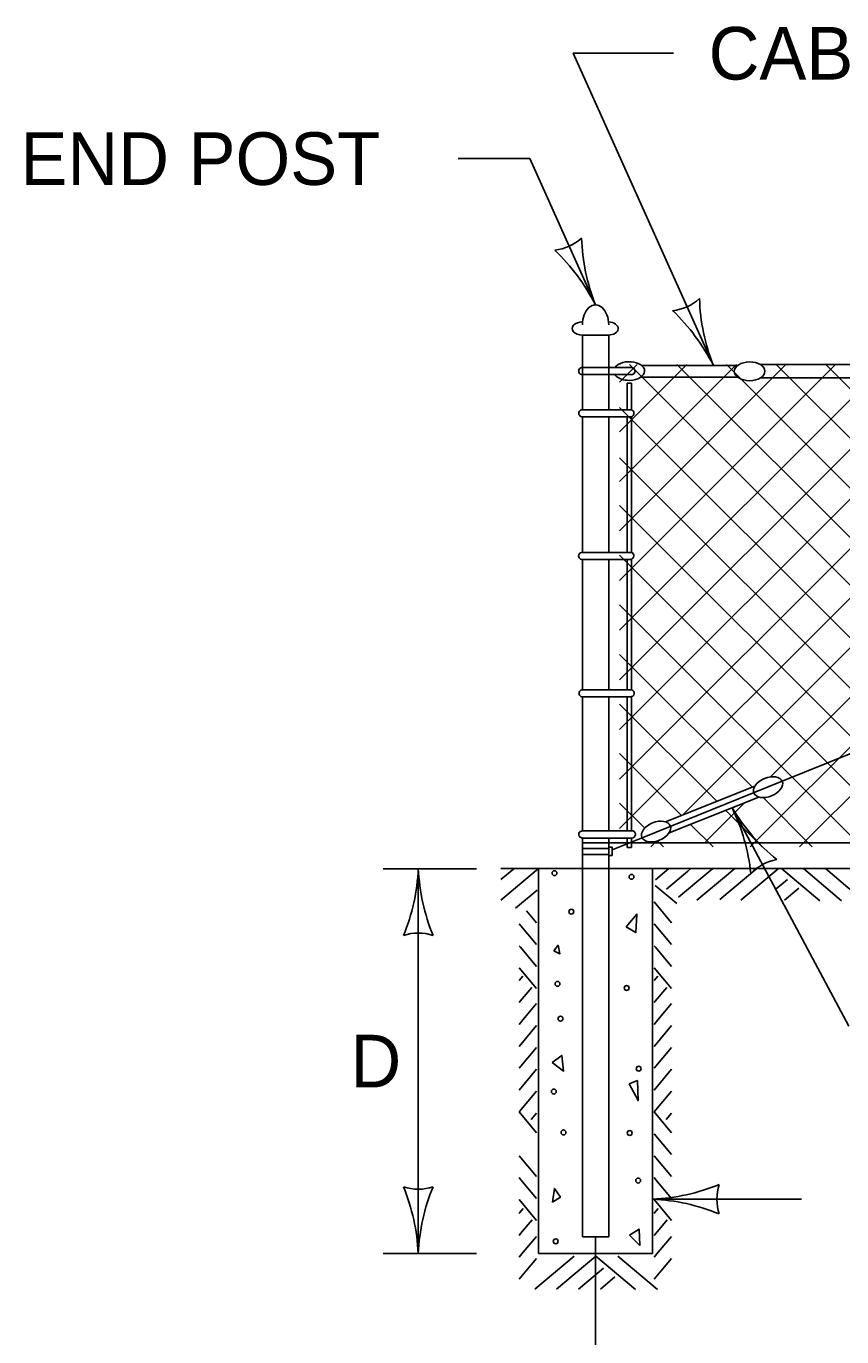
# Model space of a CAD drawing. Extents: x 49973.1 to 50021, y 49987.6 to 50015.4.
# Drawn here: x 49973.089 to 49974.019, y 50008.477 to 50009.972 of the extents above; entities that cross this region are included whole.
import ezdxf

# ---------------------------------------------------------------- set-up
doc = ezdxf.new("R2010")
doc.units = 0
for name, color, linetype in [('Level 1', 7, 'Continuous'), ('Level 2', 7, 'Continuous'), ('Level 3', 7, 'Continuous')]:
    doc.layers.add(name, color=color, linetype=linetype)

msp = doc.modelspace()

# ---------------------------------------------------------------- linework, layer by layer
at = {"layer": 'Level 1'}
for p, q in [((49973.7532, 50009.6195), (49973.7232, 50009.6195)), ((49973.7232, 50009.6195), (49973.7232, 50009.5341)), ((49973.7532, 50009.6195), (49973.7532, 50009.5341)), ((49973.7792, 50009.5824), (49973.7221, 50009.5824)), ((49973.7657, 50009.2828), (49974.0686, 50009.5857)), ((49973.7657, 50009.113), (49974.2384, 50009.5857)), ((49973.7657, 50009.2262), (49974.1252, 50009.5857)), ((49973.7657, 50009.1696), (49974.1818, 50009.5857)), ((49973.7657, 50009.0566), (49974.2948, 50009.5857)), ((49973.7657, 50009.509), (49973.8424, 50009.5857)), ((49973.7657, 50009.396), (49973.9554, 50009.5857)), ((49973.7657, 50009.4526), (49973.8988, 50009.5857)), ((49973.7657, 50009.5656), (49973.7858, 50009.5857)), ((49973.7657, 50009.3394), (49974.012, 50009.5857)), ((49973.7769, 50009.5857), (49974.3269, 50009.0357)), ((49973.9004, 50009.5848), (49973.7908, 50009.5847)), ((49973.8311, 50009.5857), (49974.3811, 50009.0357)), ((49973.8378, 50009.0721), (49974.3514, 50009.5857)), ((49973.8876, 50009.5857), (49974.0138, 50009.4595)), ((49973.9146, 50009.0357), (49974.4646, 50009.5857)), ((49973.9263, 50009.5857), (49975.6696, 50009.5857)), ((49973.9377, 50009.1154), (49974.408, 50009.5857)), ((49973.9443, 50009.5857), (49974.0683, 50009.4618)), ((49973.971, 50009.0357), (49974.521, 50009.5857)), ((49974.0009, 50009.5857), (49974.5509, 50009.0357)), ((49973.7792, 50009.5743), (49973.7223, 50009.5743)), ((49973.7742, 50009.5647), (49973.7742, 50009.5341)), ((49973.7792, 50009.5647), (49973.7742, 50009.5647)), ((49973.7792, 50009.5647), (49973.7792, 50009.5341)), ((49973.9002, 50009.5714), (49973.7897, 50009.5714)), ((49973.9265, 50009.5707), (49975.0922, 50009.5707)), ((49973.9511, 50009.1105), (49975.0483, 50009.5538)), ((49973.7231, 50009.5341), (49973.7793, 50009.5341)), ((49973.7657, 50009.5367), (49974.2667, 50009.0357)), ((49973.7231, 50009.526), (49973.7791, 50009.526)), ((49973.7232, 50009.526), (49973.7232, 50009.3716)), ((49973.7532, 50009.526), (49973.7532, 50009.3716)), ((49973.7742, 50009.526), (49973.7742, 50009.3716)), ((49973.7792, 50009.5262), (49973.7792, 50009.3716)), ((49973.7657, 50009.4795), (49974.2095, 50009.0357)), ((49974.0138, 50009.4595), (49974.4379, 50009.0357)), ((49973.7657, 50009.425), (49974.1549, 50009.0357)), ((49973.7229, 50009.3716), (49973.7791, 50009.3716)), ((49973.7657, 50009.3684), (49974.0984, 50009.0357)), ((49973.7229, 50009.3635), (49973.7789, 50009.3635)), ((49973.7232, 50009.3635), (49973.7232, 50009.2481)), ((49973.7532, 50009.3635), (49973.7532, 50009.2481)), ((49973.7742, 50009.3635), (49973.7742, 50009.2401)), ((49973.7792, 50009.3635), (49973.7792, 50009.2479)), ((49973.7657, 50009.3118), (49974.0419, 50009.0357)), ((49973.7232, 50009.2481), (49973.7232, 50009.2148)), ((49973.7532, 50009.2481), (49973.7532, 50009.2148)), ((49973.7657, 50009.2552), (49973.7801, 50009.2408)), ((49973.7792, 50009.2479), (49973.7792, 50009.2148)), ((49973.7742, 50009.2401), (49973.7742, 50009.2148)), ((49973.7801, 50009.2408), (49973.9172, 50009.1038)), ((49973.7232, 50009.2067), (49973.7232, 50009.0538)), ((49973.7234, 50009.2148), (49973.7796, 50009.2148)), ((49973.7237, 50009.2067), (49973.7783, 50009.2067)), ((49973.7532, 50009.2067), (49973.7532, 50009.0538)), ((49973.7742, 50009.2067), (49973.7742, 50009.0538)), ((49973.7792, 50009.2068), (49973.7792, 50009.0538)), ((49973.7657, 50009.1986), (49973.8766, 50009.0876)), ((49973.7657, 50009.1422), (49973.8364, 50009.0715)), ((49973.7914, 50009.046), (49973.9511, 50009.1105)), ((49973.9197, 50009.1048), (49973.8181, 50009.0642)), ((49973.7657, 50009.0856), (49973.7941, 50009.0573)), ((49973.9244, 50009.0923), (49973.8221, 50009.0515)), ((49973.8635, 50009.0412), (49973.9081, 50009.0858)), ((49973.9292, 50009.0918), (49973.9853, 50009.0357)), ((49973.8869, 50009.0773), (49973.9284, 50009.0358)), ((49973.7234, 50009.0538), (49973.7809, 50009.0538)), ((49973.8466, 50009.0613), (49973.8722, 50009.0357)), ((49973.7232, 50009.0457), (49973.7232, 50008.5909)), ((49973.7232, 50009.0402), (49975.6696, 50009.0402)), ((49973.7234, 50009.0457), (49973.7796, 50009.0457)), ((49973.7532, 50009.0457), (49973.7532, 50008.5909)), ((49973.757, 50009.0321), (49973.7914, 50009.046)), ((49973.7742, 50009.0457), (49973.7742, 50009.0348)), ((49973.7792, 50009.0457), (49973.7792, 50009.0348)), ((49973.8014, 50009.0357), (49973.8074, 50009.0417)), ((49973.8091, 50009.0422), (49973.8156, 50009.0357)), ((49973.7231, 50009.0338), (49973.7532, 50009.0338)), ((49973.7233, 50009.0269), (49973.7532, 50009.0269)), ((49973.7742, 50009.0348), (49973.7792, 50009.0348)), ((49973.6303, 50008.9748), (49973.6732, 50009.0108)), ((49973.6732, 50009.0108), (49973.6303, 50009.0108)), ((49973.6303, 50008.9983), (49973.645, 50009.0107)), ((49973.6732, 50009.0109), (49973.6732, 50008.5718)), ((49973.6732, 50009.0109), (49973.8032, 50009.0109)), ((49973.6809, 50009.0108), (49973.6832, 50009.0108)), ((49975.0779, 50009.0109), (49973.8032, 50009.0109)), ((49973.8032, 50009.0109), (49973.8032, 50008.5718)), ((49973.8065, 50008.998), (49973.8219, 50009.0108)), ((49973.819, 50008.9875), (49973.8436, 50009.0081)), ((49973.8436, 50009.0081), (49973.8469, 50009.0108)), ((49973.8652, 50009.0052), (49973.872, 50009.0108)), ((49973.8799, 50008.9756), (49973.922, 50009.0108)), ((49973.8853, 50009.001), (49973.897, 50009.0108)), ((49973.9038, 50008.9747), (49973.9469, 50009.0108)), ((49973.9412, 50009.006), (49973.9469, 50009.0108)), ((49973.9939, 50008.9742), (49973.9504, 50009.0108)), ((49974.0189, 50008.9742), (49973.9754, 50009.0108)), ((49974.0439, 50008.9742), (49974.0004, 50009.0108)), ((49973.8329, 50008.9781), (49973.8652, 50009.0052)), ((49973.8538, 50008.9747), (49973.8853, 50009.001)), ((49973.9443, 50008.9877), (49973.9572, 50008.9985)), ((49973.6469, 50008.9658), (49973.6715, 50008.9864)), ((49973.8309, 50008.9711), (49973.8063, 50008.9917)), ((49973.9038, 50008.9747), (49973.9212, 50008.9893)), ((49973.9538, 50008.9747), (49973.9701, 50008.9884)), ((49973.671, 50008.9491), (49973.6595, 50008.9628)), ((49973.825, 50008.9491), (49973.8051, 50008.9728)), ((49973.671, 50008.9241), (49973.6511, 50008.9478)), ((49973.825, 50008.9241), (49973.8051, 50008.9478)), ((49973.6526, 50008.9211), (49973.6511, 50008.9228)), ((49973.671, 50008.8991), (49973.6526, 50008.9211)), ((49973.8066, 50008.9211), (49973.8051, 50008.9228)), ((49973.825, 50008.8991), (49973.8066, 50008.9211)), ((49973.6552, 50008.8881), (49973.651, 50008.8831)), ((49973.671, 50008.8741), (49973.6511, 50008.8978)), ((49973.8092, 50008.8881), (49973.805, 50008.8831)), ((49973.825, 50008.8741), (49973.8051, 50008.8978)), ((49973.6654, 50008.8754), (49973.6523, 50008.8597)), ((49973.8194, 50008.8754), (49973.8063, 50008.8597)), ((49973.6523, 50008.8597), (49973.6511, 50008.8582)), ((49973.8063, 50008.8597), (49973.8051, 50008.8582)), ((49973.671, 50008.857), (49973.6553, 50008.8383)), ((49973.825, 50008.857), (49973.8093, 50008.8383)), ((49973.6553, 50008.8383), (49973.6511, 50008.8332)), ((49973.671, 50008.8319), (49973.6582, 50008.8167)), ((49973.8093, 50008.8383), (49973.8051, 50008.8332)), ((49973.825, 50008.8319), (49973.8122, 50008.8167)), ((49973.6582, 50008.8167), (49973.6511, 50008.8081)), ((49973.8122, 50008.8167), (49973.8051, 50008.8081)), ((49973.671, 50008.8069), (49973.6511, 50008.7831)), ((49973.825, 50008.8069), (49973.8051, 50008.7831)), ((49973.671, 50008.7819), (49973.6511, 50008.7581)), ((49973.825, 50008.7819), (49973.8051, 50008.7581)), ((49973.671, 50008.757), (49973.6511, 50008.7333)), ((49973.825, 50008.757), (49973.8051, 50008.7333)), ((49973.671, 50008.7096), (49973.6511, 50008.7333)), ((49973.671, 50008.7319), (49973.6649, 50008.7247)), ((49973.825, 50008.7096), (49973.8051, 50008.7333)), ((49973.825, 50008.7319), (49973.8189, 50008.7247)), ((49973.825, 50008.6846), (49973.8051, 50008.7083)), ((49973.671, 50008.6596), (49973.6511, 50008.6833)), ((49973.825, 50008.6596), (49973.8051, 50008.6833)), ((49973.6531, 50008.656), (49973.6511, 50008.6583)), ((49973.671, 50008.6346), (49973.6531, 50008.656)), ((49973.8071, 50008.656), (49973.8051, 50008.6583)), ((49973.825, 50008.6346), (49973.8071, 50008.656)), ((49973.671, 50008.6096), (49973.6511, 50008.6333)), ((49973.825, 50008.6096), (49973.8051, 50008.6333)), ((49973.6557, 50008.623), (49973.6515, 50008.618)), ((49973.8097, 50008.623), (49973.8055, 50008.618)), ((49973.6515, 50008.618), (49973.6511, 50008.6175)), ((49973.6659, 50008.6103), (49973.6528, 50008.5946)), ((49973.8055, 50008.618), (49973.8051, 50008.6175)), ((49973.8199, 50008.6103), (49973.8068, 50008.5946)), ((49973.6528, 50008.5946), (49973.6511, 50008.5925)), ((49973.671, 50008.5913), (49973.6558, 50008.5732)), ((49973.7232, 50008.5909), (49973.7532, 50008.5909)), ((49973.7382, 50008.5909), (49973.7382, 50008.5903)), ((49973.8068, 50008.5946), (49973.8051, 50008.5925)), ((49973.825, 50008.5913), (49973.8098, 50008.5732)), ((49973.6558, 50008.5732), (49973.6511, 50008.5675)), ((49973.8098, 50008.5732), (49973.8051, 50008.5675)), ((49973.671, 50008.5662), (49973.6587, 50008.5516)), ((49973.6688, 50008.5313), (49973.7138, 50008.5689)), ((49973.6732, 50008.5718), (49973.8032, 50008.5718)), ((49973.6938, 50008.5313), (49973.7386, 50008.5689)), ((49973.7839, 50008.5308), (49973.7386, 50008.5689)), ((49973.8089, 50008.5308), (49973.7636, 50008.5689)), ((49973.825, 50008.5662), (49973.8127, 50008.5516)), ((49973.6587, 50008.5516), (49973.6511, 50008.5424)), ((49973.7188, 50008.5313), (49973.7472, 50008.5551)), ((49973.7438, 50008.5313), (49973.7601, 50008.545)), ((49973.8127, 50008.5516), (49973.8051, 50008.5424))]:
    msp.add_line(p, q, dxfattribs=at)
for points in [[(49973.7532, 50009.0354), (49973.7532, 50009.0258), (49973.757, 50009.0258), (49973.757, 50009.0354)], [(49973.773, 50008.9446), (49973.7854, 50008.959), (49973.784, 50008.9378)], [(49973.6907, 50008.9172), (49973.6955, 50008.9234), (49973.6975, 50008.9138)], [(49973.6886, 50008.7896), (49973.6996, 50008.7978), (49973.7017, 50008.7799)], [(49973.7764, 50008.7655), (49973.786, 50008.769), (49973.7867, 50008.7463)], [(49973.6893, 50008.6304), (49973.6914, 50008.6461), (49973.6982, 50008.6359)], [(49973.7771, 50008.5926), (49973.7881, 50008.5995), (49973.7888, 50008.581)]]:
    msp.add_lwpolyline(points, close=True, dxfattribs=at)
for centre in [(49973.6914, 50009.0056), (49973.7792, 50009.0015), (49973.7106, 50008.9617), (49973.6948, 50008.8794), (49973.7737, 50008.8746), (49973.6982, 50008.8396), (49973.7874, 50008.7826), (49973.6907, 50008.7565), (49973.7017, 50008.7099), (49973.7772, 50008.7092), (49973.7868, 50008.655), (49973.6928, 50008.5857)]:
    msp.add_circle(centre, 0.00279, dxfattribs=at)
for centre, radius, start, end in [((49973.7232, 50009.5784), 0.00417, 104.8473, 257.4184), ((49973.7792, 50009.5783), 0.00405, 269.3348, 90.4595), ((49973.7232, 50009.5301), 0.00405, 87.9212, 274.9002), ((49973.7779, 50009.5302), 0.00417, 282.5816, 72.0167), ((49973.723, 50009.3676), 0.00405, 87.9212, 274.9002), ((49973.7777, 50009.3677), 0.00417, 282.5816, 72.0167), ((49973.7235, 50009.2108), 0.00405, 87.9212, 273.176), ((49973.7782, 50009.2109), 0.00417, 270.4471, 70.4979), ((49973.7232, 50009.0498), 0.00405, 87.9212, 273.176), ((49973.7795, 50009.0499), 0.00417, 270.4471, 70.4979)]:
    msp.add_arc(centre, radius, start, end, dxfattribs=at)
for centre, major_axis, ratio, start_param, end_param in [((49973.7382, 50009.6312), (0, -0.0226), 0.66398, 1.570796, 4.712389), ((49973.7231, 50009.6269), (0.0115, 0.0001), 0.649749, 1.548884, 4.712389), ((49973.7526, 50009.6269), (0.0115, -0.0001), 0.649749, 4.712389, 7.82351), ((49973.7766, 50009.5784), (0.0175, 0.0001), 0.610393, 4.569027, 9.026485), ((49973.7766, 50009.5784), (0.0175, 0.0001), 0.610393, 3.521347, 4.569027)]:
    msp.add_ellipse(centre, major_axis=major_axis, ratio=ratio, start_param=start_param, end_param=end_param, dxfattribs=at)
for centre, major_axis in [((49973.9139, 50009.5781), (0.0175, 0.0001)), ((49973.935, 50009.1037), (0.0162, 0.0066)), ((49973.8073, 50009.0531), (0.0162, 0.0066))]:
    msp.add_ellipse(centre, major_axis=major_axis, ratio=0.610393, dxfattribs=at)
at = {"layer": 'Level 3'}
for p, q in [((49973.8272, 50009.9409), (49973.7128, 50009.9409)), ((49973.8726, 50009.5848), (49973.7128, 50009.9409)), ((49973.6633, 50009.8207), (49973.5816, 50009.8207)), ((49973.7382, 50009.6538), (49973.6633, 50009.8207)), ((49973.894, 50009.0802), (49974.0272, 50008.8313)), ((49973.6025, 50009.0107), (49973.4961, 50009.0107)), ((49973.5361, 50008.5718), (49973.5361, 50009.0107)), ((49973.9731, 50008.6337), (49973.8032, 50008.6337)), ((49973.7382, 50008.5718), (49973.7382, 50008.5903)), ((49973.6025, 50008.5718), (49973.4961, 50008.5718)), ((49973.7382, 50008.5718), (49973.7382, 50008.2315))]:
    msp.add_line(p, q, dxfattribs=at)
for centre, radius, start, end in [((49973.6857, 50009.7708), 0.0548, 276.308, 312.0304), ((49973.9446, 50009.7364), 0.2223, 181.6252, 201.8087), ((49973.5305, 50009.548), 0.233, 26.9965, 46.2464), ((49973.8201, 50009.7017), 0.0548, 276.308, 312.0304), ((49974.079, 50009.6674), 0.2223, 181.6252, 201.8087), ((49973.665, 50009.479), 0.233, 26.9965, 46.2464), ((49973.694, 50008.983), 0.2223, 5.746, 25.9295), ((49974.0934, 50009.2006), 0.233, 211.1173, 230.3671), ((49973.3139, 50009.0199), 0.2223, 337.456, 357.6395), ((49973.7688, 50009.0222), 0.233, 182.8273, 202.0772), ((49973.9547, 50008.9673), 0.0548, 100.4288, 136.1511), ((49973.5361, 50008.8825), 0.0548, 72.1388, 107.8612), ((49973.7917, 50008.8664), 0.233, 272.8273, 292.0772), ((49973.9314, 50008.6337), 0.0548, 162.1388, 197.8612), ((49973.5361, 50008.7), 0.0548, 252.1388, 287.8612), ((49973.3033, 50008.5603), 0.233, 2.8273, 22.0772), ((49973.7582, 50008.5627), 0.2223, 157.456, 177.6395), ((49973.794, 50008.4116), 0.2223, 67.456, 87.6395)]:
    msp.add_arc(centre, radius, start, end, dxfattribs=at)

# ---------------------------------------------------------------- texts
at = {"layer": 'Level 2'}
msp.add_text('CABLE TURNBUCKLE', height=0.06, rotation=360, dxfattribs=at).set_placement((49973.8672, 50009.9109))
for s, p in [('END POST', (49973.0824, 50009.7907)), ('D', (49973.4587, 50008.7613))]:
    msp.add_text(s, height=0.06, dxfattribs=at).set_placement(p)

doc.saveas('drawing.dxf')
